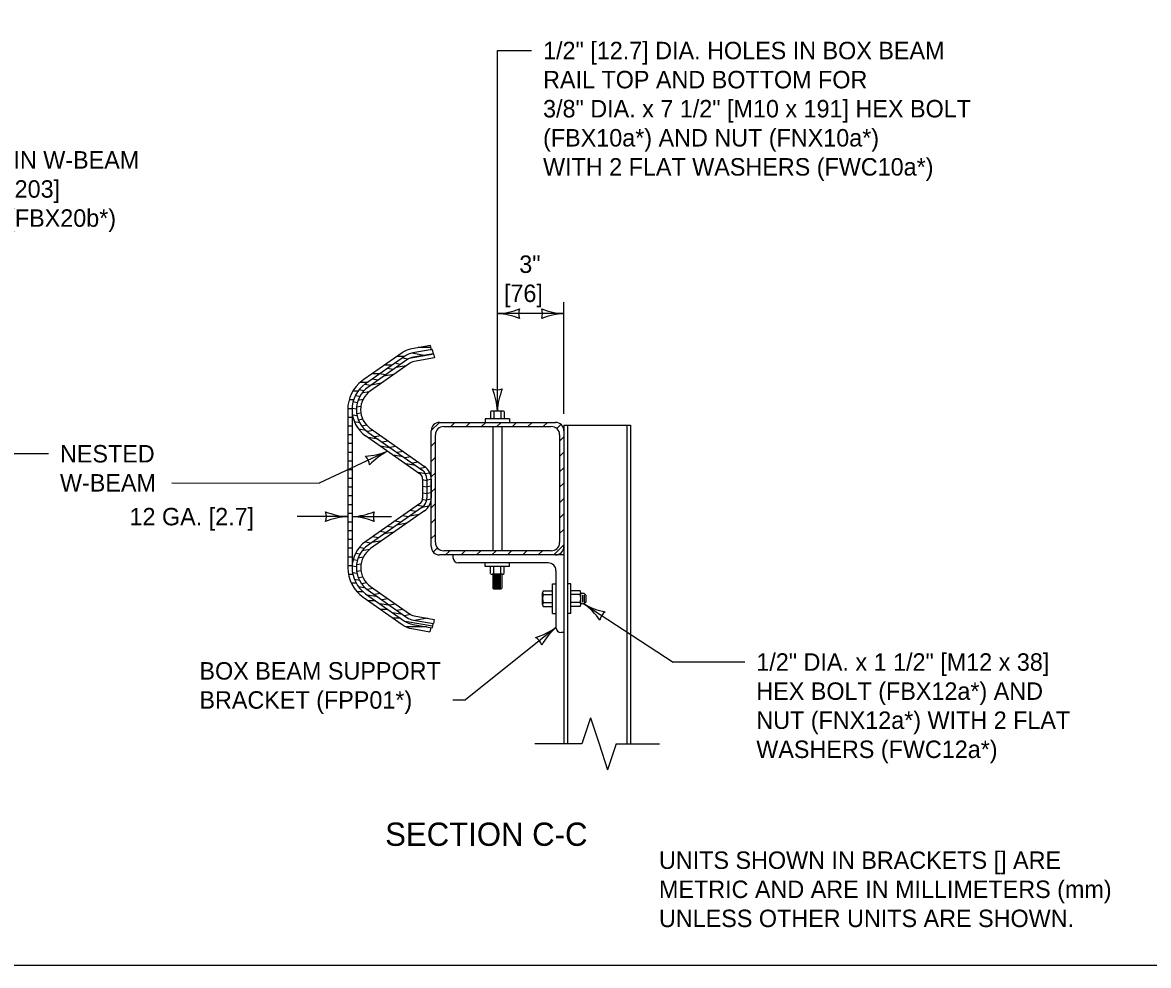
# Model space of a CAD drawing. Extents: x 49991.4 to 50021, y 49987.6 to 50011.4.
# Drawn here: x 50009.364 to 50013.234, y 49987.799 to 49991.041 of the extents above; entities that cross this region are included whole.
import ezdxf

# ---------------------------------------------------------------- set-up
doc = ezdxf.new("R2010")
doc.units = 0
for name, color, linetype in [('Level 1', 7, 'Continuous'), ('Level 2', 7, 'Continuous'), ('Level 3', 7, 'Continuous'), ('Level 6', 7, 'Continuous')]:
    doc.layers.add(name, color=color, linetype=linetype)

msp = doc.modelspace()

# ---------------------------------------------------------------- linework, layer by layer
at = {"layer": 'Level 1'}
for p, q in [((50010.6684, 49989.9052), (50010.5369, 49989.8129)), ((50010.7771, 49989.9002), (50010.6931, 49989.8853)), ((50010.7439, 49989.8964), (50010.7016, 49989.9038)), ((50010.7667, 49989.9304), (50010.7024, 49989.9192)), ((50010.7723, 49989.9164), (50010.7049, 49989.9046)), ((50010.7768, 49989.9021), (50010.7075, 49989.89)), ((50010.7682, 49989.923), (50010.7239, 49989.923)), ((50010.7728, 49989.9139), (50010.7654, 49989.9152)), ((50010.7698, 49989.9159), (50010.7667, 49989.9304)), ((50010.7723, 49989.9164), (50010.7748, 49989.9018)), ((50010.7768, 49989.9021), (50010.7794, 49989.8875)), ((50010.6769, 49989.893), (50010.5424, 49989.7987)), ((50010.6854, 49989.8809), (50010.5509, 49989.7865)), ((50010.6939, 49989.8688), (50010.5594, 49989.7744)), ((50010.634, 49989.863), (50010.6082, 49989.863)), ((50010.6633, 49989.8654), (50010.6427, 49989.8691)), ((50010.6827, 49989.8609), (50010.6482, 49989.8548)), ((50010.6768, 49989.893), (50010.651, 49989.893)), ((50010.6894, 49989.8834), (50010.6684, 49989.8871)), ((50010.7794, 49989.8875), (50010.71, 49989.8754)), ((50010.5912, 49989.833), (50010.5655, 49989.833)), ((50010.6118, 49989.8293), (50010.5912, 49989.833)), ((50010.6396, 49989.8307), (50010.6051, 49989.8246)), ((50010.6376, 49989.8474), (50010.6169, 49989.851)), ((50010.5375, 49989.7747), (50010.5204, 49989.7777)), ((50010.5484, 49989.803), (50010.524, 49989.803)), ((50010.5369, 49989.8129), (50010.5313, 49989.809)), ((50010.5603, 49989.7932), (50010.54, 49989.7968)), ((50010.5424, 49989.7987), (50010.543, 49989.7992)), ((50010.5966, 49989.8006), (50010.5621, 49989.7945)), ((50010.5861, 49989.8113), (50010.5654, 49989.8149)), ((50010.5019, 49989.743), (50010.4863, 49989.743)), ((50010.5169, 49989.773), (50010.4992, 49989.773)), ((50010.5229, 49989.7546), (50010.5075, 49989.7574)), ((50010.5343, 49989.7444), (50010.517, 49989.7413)), ((50010.5547, 49989.7706), (50010.5303, 49989.7663)), ((50010.4816, 49989.7096), (50010.4819, 49989.1665)), ((50010.4966, 49989.713), (50010.4819, 49989.713)), ((50010.4964, 49989.7096), (50010.4967, 49989.1665)), ((50010.5114, 49989.7115), (50010.4967, 49989.7141)), ((50010.5145, 49989.7335), (50010.4999, 49989.7361)), ((50010.5271, 49989.7205), (50010.5118, 49989.7178)), ((50010.9719, 49989.7033), (50010.9719, 49989.6781)), ((50011.0139, 49989.7048), (50010.978, 49989.7048)), ((50010.9838, 49989.7034), (50010.9838, 49989.6781)), ((50011.008, 49989.7034), (50011.008, 49989.6781)), ((50011.0199, 49989.7033), (50011.0199, 49989.6781)), ((50010.4965, 49989.683), (50010.4817, 49989.683)), ((50010.5139, 49989.6885), (50010.4981, 49989.6912)), ((50010.5231, 49989.6643), (50010.5052, 49989.6674)), ((50010.5272, 49989.698), (50010.5124, 49989.6954)), ((50010.5335, 49989.6765), (50010.5184, 49989.6738)), ((50010.7685, 49989.6377), (50010.797, 49989.6661)), ((50010.7973, 49989.6661), (50011.1957, 49989.6661)), ((50010.8356, 49989.6517), (50010.85, 49989.6661)), ((50010.8886, 49989.6517), (50010.903, 49989.6661)), ((50010.9417, 49989.6517), (50010.9561, 49989.6661)), ((50010.9539, 49989.6781), (50010.9539, 49989.6661)), ((50011.0379, 49989.6781), (50010.9539, 49989.6781)), ((50010.9947, 49989.6517), (50011.0091, 49989.6661)), ((50011.0379, 49989.6781), (50011.0379, 49989.6661)), ((50011.0477, 49989.6517), (50011.0621, 49989.6661)), ((50011.1008, 49989.6517), (50011.1152, 49989.6661)), ((50011.1538, 49989.6517), (50011.1682, 49989.6661)), ((50010.4965, 49989.653), (50010.4817, 49989.653)), ((50010.4965, 49989.623), (50010.4817, 49989.623)), ((50010.5445, 49989.6379), (50010.5199, 49989.6422)), ((50010.5469, 49989.6563), (50010.5301, 49989.6533)), ((50010.5696, 49989.6377), (50010.5492, 49989.6341)), ((50010.5509, 49989.6328), (50010.7369, 49989.5026)), ((50010.5594, 49989.6449), (50010.7454, 49989.5148)), ((50010.7685, 49989.2389), (50010.7685, 49989.6373)), ((50010.7829, 49989.2533), (50010.7829, 49989.6229)), ((50010.8117, 49989.6517), (50011.1813, 49989.6517)), ((50010.9809, 49989.6517), (50010.9809, 49989.2245)), ((50011.0109, 49989.6517), (50011.0109, 49989.2245)), ((50011.2, 49989.6449), (50011.2144, 49989.6593)), ((50011.2101, 49989.6229), (50011.2101, 49989.2533)), ((50011.2245, 49989.6559), (50011.4531, 49989.6559)), ((50011.2245, 49989.6559), (50011.2245, 49988.5606)), ((50011.2245, 49989.6373), (50011.2245, 49989.2389)), ((50011.2365, 49989.6559), (50011.2365, 49988.5606)), ((50011.4411, 49989.6559), (50011.4411, 49988.5606)), ((50011.4531, 49989.6559), (50011.4531, 49988.5606)), ((50010.4965, 49989.593), (50010.4817, 49989.593)), ((50010.5431, 49989.62), (50010.5424, 49989.6206)), ((50010.5424, 49989.6206), (50010.7284, 49989.4905)), ((50010.5862, 49989.6079), (50010.5516, 49989.614)), ((50010.5954, 49989.6196), (50010.5747, 49989.616)), ((50010.6212, 49989.6016), (50010.6005, 49989.5979)), ((50010.7685, 49989.5846), (50010.7829, 49989.599)), ((50011.2101, 49989.602), (50011.2245, 49989.6164)), ((50010.4965, 49989.563), (50010.4817, 49989.563)), ((50010.6294, 49989.5777), (50010.5948, 49989.5838)), ((50010.647, 49989.5835), (50010.6263, 49989.5799)), ((50010.6726, 49989.5475), (50010.638, 49989.5536)), ((50010.6728, 49989.5655), (50010.6521, 49989.5619)), ((50010.6986, 49989.5475), (50010.6779, 49989.5438)), ((50010.7685, 49989.5316), (50010.7829, 49989.546)), ((50011.2101, 49989.5489), (50011.2245, 49989.5633)), ((50010.4965, 49989.533), (50010.4817, 49989.533)), ((50010.7159, 49989.5173), (50010.6812, 49989.5234)), ((50010.7244, 49989.5294), (50010.7037, 49989.5258)), ((50010.7495, 49989.5113), (50010.7295, 49989.5077)), ((50011.2101, 49989.4959), (50011.2245, 49989.5103)), ((50010.4965, 49989.503), (50010.4817, 49989.503)), ((50010.4966, 49989.473), (50010.4818, 49989.473)), ((50010.7489, 49989.4889), (50010.7245, 49989.4932)), ((50010.7389, 49989.4703), (50010.7389, 49989.4381)), ((50010.7537, 49989.4655), (50010.7389, 49989.4681)), ((50010.7642, 49989.4913), (50010.749, 49989.4886)), ((50010.7537, 49989.4703), (50010.7537, 49989.4381)), ((50010.7685, 49989.4694), (50010.7537, 49989.4668)), ((50010.7685, 49989.4786), (50010.7829, 49989.493)), ((50010.7685, 49989.4703), (50010.7685, 49989.4381)), ((50010.4966, 49989.443), (50010.4818, 49989.443)), ((50010.7537, 49989.4429), (50010.7389, 49989.4455)), ((50010.7389, 49989.4381), (50010.7389, 49989.4059)), ((50010.7685, 49989.4468), (50010.7537, 49989.4442)), ((50010.7537, 49989.4381), (50010.7537, 49989.4059)), ((50010.7685, 49989.4381), (50010.7685, 49989.4059)), ((50010.7686, 49989.4256), (50010.7829, 49989.4399)), ((50011.2101, 49989.4429), (50011.2245, 49989.4573)), ((50010.4966, 49989.413), (50010.4818, 49989.413)), ((50010.7528, 49989.3978), (50010.7381, 49989.4004)), ((50010.7537, 49989.4203), (50010.7389, 49989.4229)), ((50010.7681, 49989.4016), (50010.7529, 49989.3989)), ((50010.7685, 49989.4243), (50010.7537, 49989.4216)), ((50011.2101, 49989.3898), (50011.2245, 49989.4042)), ((50010.4966, 49989.383), (50010.4818, 49989.383)), ((50010.4966, 49989.353), (50010.4818, 49989.353)), ((50010.7284, 49989.3857), (50010.5434, 49989.2562)), ((50010.7369, 49989.3736), (50010.5519, 49989.2441)), ((50010.7454, 49989.3614), (50010.5604, 49989.2319)), ((50010.7162, 49989.3591), (50010.6956, 49989.3628)), ((50010.7412, 49989.3773), (50010.7213, 49989.3808)), ((50010.7606, 49989.3777), (50010.7367, 49989.3735)), ((50010.7685, 49989.3725), (50010.7829, 49989.3869)), ((50010.4966, 49989.323), (50010.4818, 49989.323)), ((50010.6647, 49989.323), (50010.644, 49989.3267)), ((50010.685, 49989.3192), (50010.6505, 49989.3131)), ((50010.6905, 49989.3411), (50010.6698, 49989.3447)), ((50010.7282, 49989.3494), (50010.6936, 49989.3433)), ((50010.7685, 49989.3195), (50010.7829, 49989.3339)), ((50011.2101, 49989.3368), (50011.2245, 49989.3512)), ((50010.4966, 49989.293), (50010.4818, 49989.293)), ((50010.6131, 49989.2869), (50010.5925, 49989.2906)), ((50010.6419, 49989.289), (50010.6073, 49989.2829)), ((50010.6389, 49989.305), (50010.6182, 49989.3086)), ((50010.7685, 49989.2664), (50010.7829, 49989.2808)), ((50011.2101, 49989.2838), (50011.2245, 49989.2982)), ((50010.4967, 49989.263), (50010.4819, 49989.263)), ((50010.5616, 49989.2509), (50010.5411, 49989.2545)), ((50010.5988, 49989.2588), (50010.5642, 49989.2527)), ((50010.5874, 49989.2689), (50010.5667, 49989.2725)), ((50011.1895, 49989.2101), (50011.2245, 49989.2451)), ((50010.4967, 49989.233), (50010.4819, 49989.233)), ((50010.4967, 49989.203), (50010.4819, 49989.203)), ((50010.5236, 49989.2124), (50010.5082, 49989.2151)), ((50010.5351, 49989.2024), (50010.5176, 49989.1993)), ((50010.5384, 49989.2323), (50010.5212, 49989.2354)), ((50010.5565, 49989.2287), (50010.5314, 49989.2243)), ((50010.7754, 49989.2203), (50010.7898, 49989.2347)), ((50011.1957, 49989.2101), (50010.7973, 49989.2101)), ((50011.1813, 49989.2245), (50010.8117, 49989.2245)), ((50010.8183, 49989.2101), (50010.8327, 49989.2245)), ((50011.2245, 49989.2101), (50010.8435, 49989.2101)), ((50010.8435, 49989.2101), (50010.8435, 49989.2011)), ((50010.8713, 49989.2101), (50010.8857, 49989.2245)), ((50010.9243, 49989.2101), (50010.9387, 49989.2245)), ((50010.9774, 49989.2101), (50010.9918, 49989.2245)), ((50011.0304, 49989.2101), (50011.0448, 49989.2245)), ((50011.0834, 49989.2101), (50011.0978, 49989.2245)), ((50011.1365, 49989.2101), (50011.1509, 49989.2245)), ((50010.4967, 49989.173), (50010.4819, 49989.173)), ((50010.5117, 49989.1693), (50010.4969, 49989.1719)), ((50010.5149, 49989.1913), (50010.5004, 49989.1939)), ((50010.5275, 49989.1784), (50010.5122, 49989.1757)), ((50011.1705, 49989.1831), (50010.8615, 49989.1831)), ((50010.9539, 49989.1711), (50010.9539, 49989.1831)), ((50011.0379, 49989.1711), (50010.9539, 49989.1711)), ((50010.9719, 49989.1459), (50010.9719, 49989.1711)), ((50010.9838, 49989.1458), (50010.9838, 49989.1711)), ((50011.008, 49989.1458), (50011.008, 49989.1711)), ((50011.0199, 49989.1459), (50011.0199, 49989.1711)), ((50011.0379, 49989.1711), (50011.0379, 49989.1831)), ((50010.4996, 49989.143), (50010.4845, 49989.143)), ((50010.5139, 49989.1463), (50010.4983, 49989.1491)), ((50010.5228, 49989.1221), (50010.505, 49989.1253)), ((50010.5273, 49989.1558), (50010.5125, 49989.1532)), ((50010.5333, 49989.1343), (50010.5184, 49989.1317)), ((50011.0139, 49989.1444), (50010.978, 49989.1444)), ((50010.9809, 49989.1444), (50010.9809, 49989.0961)), ((50011.0079, 49989.1411), (50010.9839, 49989.1411)), ((50011.0079, 49989.1366), (50010.9839, 49989.1366)), ((50011.0079, 49989.1321), (50010.9839, 49989.1321)), ((50011.0079, 49989.1276), (50010.9839, 49989.1276)), ((50011.0079, 49989.1231), (50010.9839, 49989.1231)), ((50011.0109, 49989.1444), (50011.0109, 49989.0961)), ((50011.1975, 49989.1561), (50011.1975, 49988.9611)), ((50010.5111, 49989.113), (50010.4943, 49989.113)), ((50010.5357, 49989.083), (50010.5146, 49989.083)), ((50010.5433, 49989.0959), (50010.5194, 49989.1002)), ((50010.5463, 49989.114), (50010.5298, 49989.1111)), ((50010.5687, 49989.0954), (50010.5485, 49989.0918)), ((50010.5518, 49989.0891), (50010.6854, 49988.9952)), ((50010.5603, 49989.1012), (50010.6939, 49989.0074)), ((50010.9839, 49989.0931), (50010.9809, 49989.0961)), ((50011.0079, 49989.1186), (50010.9839, 49989.1186)), ((50011.0079, 49989.1141), (50010.9839, 49989.1141)), ((50011.0079, 49989.1096), (50010.9839, 49989.1096)), ((50011.0079, 49989.1051), (50010.9839, 49989.1051)), ((50011.0079, 49989.1006), (50010.9839, 49989.1006)), ((50011.0079, 49989.0961), (50010.9839, 49989.0961)), ((50011.0079, 49989.0931), (50010.9839, 49989.0931)), ((50011.0109, 49989.0961), (50011.0079, 49989.0931)), ((50011.1531, 49989.0871), (50011.1855, 49989.0871)), ((50011.1855, 49989.1111), (50011.1975, 49989.1111)), ((50011.1855, 49989.0091), (50011.1855, 49989.1111)), ((50011.2485, 49989.1111), (50011.2365, 49989.1111)), ((50011.2485, 49989.0091), (50011.2485, 49989.1111)), ((50011.2809, 49989.0871), (50011.2485, 49989.0871)), ((50010.5347, 49989.0649), (50010.6683, 49988.971)), ((50010.5433, 49989.077), (50010.6769, 49988.9831)), ((50010.5846, 49989.0661), (50010.5501, 49989.0722)), ((50010.5774, 49989.053), (50010.5517, 49989.053)), ((50010.5944, 49989.0773), (50010.5738, 49989.0737)), ((50010.6201, 49989.0592), (50010.5995, 49989.0556)), ((50011.1514, 49989.0399), (50011.1514, 49989.0803)), ((50011.1531, 49989.0737), (50011.1855, 49989.0737)), ((50011.1531, 49989.0465), (50011.1855, 49989.0465)), ((50011.281, 49989.0737), (50011.2485, 49989.0737)), ((50011.281, 49989.0465), (50011.2485, 49989.0465)), ((50011.2826, 49989.0399), (50011.2826, 49989.0803)), ((50011.2935, 49989.0781), (50011.2826, 49989.0781)), ((50011.289, 49989.0721), (50011.289, 49989.0481)), ((50011.2995, 49989.0721), (50011.2935, 49989.0781)), ((50011.2995, 49989.0481), (50011.2935, 49989.0421)), ((50011.2943, 49989.0721), (50011.2943, 49989.0481)), ((50011.2995, 49989.0721), (50011.2995, 49989.0481)), ((50010.6275, 49989.0359), (50010.593, 49989.042)), ((50010.6201, 49989.023), (50010.5944, 49989.023)), ((50010.6458, 49989.0412), (50010.6252, 49989.0375)), ((50010.6704, 49989.0058), (50010.636, 49989.0118)), ((50010.6715, 49989.0231), (50010.6509, 49989.0195)), ((50010.6979, 49989.0052), (50010.6766, 49989.0014)), ((50011.1531, 49989.0331), (50011.1855, 49989.0331)), ((50011.1855, 49989.0091), (50011.1975, 49989.0091)), ((50011.2485, 49989.0091), (50011.2365, 49989.0091)), ((50011.2809, 49989.0331), (50011.2485, 49989.0331)), ((50011.2935, 49989.0421), (50011.2826, 49989.0421)), ((50010.6628, 49988.993), (50010.6371, 49988.993)), ((50010.7729, 49988.9651), (50010.6793, 49988.9816)), ((50010.7049, 49988.9715), (50010.772, 49988.9598)), ((50010.7075, 49988.9861), (50010.7768, 49988.974)), ((50010.71, 49989.0008), (50010.7793, 49988.9886)), ((50010.7556, 49988.9928), (50010.7127, 49988.9852)), ((50010.7746, 49988.9744), (50010.772, 49988.9598)), ((50010.7793, 49988.9886), (50010.7768, 49988.974)), ((50010.7537, 49988.963), (50010.6833, 49988.963)), ((50010.7025, 49988.9569), (50010.7023, 49988.957)), ((50010.7023, 49988.957), (50010.7644, 49988.9461)), ((50010.7668, 49988.9607), (50010.7644, 49988.9461)), ((50011.2245, 49988.9431), (50011.2155, 49988.9431))]:
    msp.add_line(p, q, dxfattribs=at)
msp.add_lwpolyline([(49999.3835, 49998.9992), (50016.7501, 49998.9992), (50016.7501, 49987.7988), (49999.3835, 49987.7988)], close=True, dxfattribs=at)
for centre, radius, start, end in [((50010.7166, 49989.8364), 0.084, 99.7276, 125.0905), ((50010.7166, 49989.8364), 0.0692, 99.7276, 125.0905), ((50010.7166, 49989.8364), 0.0544, 99.7276, 125.0905), ((50010.7166, 49989.8364), 0.0396, 99.7276, 125.0905), ((50010.6059, 49989.7096), 0.1242, 126.8825, 180.0271), ((50010.6059, 49989.7096), 0.1094, 125.0494, 235.0019), ((50010.6059, 49989.7096), 0.0946, 125.0494, 235.0019), ((50010.6059, 49989.7096), 0.0798, 125.0494, 235.0019), ((50010.7973, 49989.6373), 0.0288, 90, 180), ((50011.1957, 49989.6373), 0.0288, 0, 90), ((50010.8117, 49989.6229), 0.0288, 90, 180), ((50011.1813, 49989.6229), 0.0288, 0, 90), ((50010.7142, 49989.4703), 0.0543, 0, 54.9777), ((50010.7142, 49989.4703), 0.0247, 0, 54.9777), ((50010.7142, 49989.4703), 0.0395, 0, 54.9777), ((50010.7142, 49989.4059), 0.0247, 305.0223, 0), ((50010.7142, 49989.4059), 0.0395, 305.0223, 0), ((50010.7142, 49989.4059), 0.0543, 305.0223, 0), ((50010.6062, 49989.1666), 0.1095, 124.9844, 234.9352), ((50010.6062, 49989.1666), 0.0946, 124.9844, 234.9352), ((50010.7973, 49989.2389), 0.0288, 180, 270), ((50010.8117, 49989.2533), 0.0288, 180, 270), ((50011.1813, 49989.2533), 0.0288, 270, 0), ((50011.1957, 49989.2389), 0.0288, 270, 0), ((50010.6062, 49989.1666), 0.0798, 124.9844, 234.9352), ((50010.8615, 49989.2011), 0.018, 180, 270), ((50010.6062, 49989.1666), 0.1243, 180.027, 234.9352), ((50011.1705, 49989.1561), 0.027, 0, 90), ((50010.7166, 49989.0397), 0.0396, 234.9095, 260.2724), ((50010.7166, 49989.0397), 0.084, 234.9095, 260.2724), ((50010.7166, 49989.0397), 0.0692, 234.9095, 260.2724), ((50010.7166, 49989.0397), 0.0544, 234.9095, 260.2724), ((50011.2155, 49988.9611), 0.018, 180, 270)]:
    msp.add_arc(centre, radius, start, end, dxfattribs=at)
for centre, major_axis, start_param, end_param in [((50010.9779, 49989.6936), (-0.012, 0), 4.198439, 5.235988), ((50010.9959, 49989.6598), (-0.048, 0), 4.457545, 4.967234), ((50011.0139, 49989.6936), (-0.012, 0), 4.188789, 5.226338), ((50010.9779, 49989.1556), (-0.012, 0), 1.047198, 2.084746), ((50010.9959, 49989.1894), (-0.048, 0), 1.315951, 1.825641), ((50011.0139, 49989.1556), (-0.012, 0), 1.056847, 2.094396), ((50011.1641, 49989.0803), (0, 0.0135), 1.047198, 2.084746), ((50011.27, 49989.0803), (0, 0.0135), 4.198439, 5.235988), ((50011.202, 49989.0601), (0, 0.054), 1.315951, 1.825641), ((50011.1641, 49989.0398), (0, 0.0135), 1.056847, 2.094396), ((50011.27, 49989.0398), (0, 0.0135), 4.188789, 5.226338), ((50011.232, 49989.0601), (0, 0.054), 4.457545, 4.967234)]:
    msp.add_ellipse(centre, major_axis=major_axis, ratio=0.93686, start_param=start_param, end_param=end_param, dxfattribs=at)
at = {"layer": 'Level 3'}
for p, q in [((50010.996, 49989.7048), (50010.996, 49990.9445)), ((50010.996, 49990.9445), (50011.1131, 49990.9445)), ((50011.2245, 49989.6959), (50011.2245, 49990.0798)), ((50011.2245, 49990.0398), (50010.996, 49990.0398)), ((50009.4528, 49989.5582), (50009.2298, 49989.5582)), ((50010.6189, 49989.5671), (50010.3839, 49989.4575)), ((50009.8772, 49989.4582), (50010.3839, 49989.4575)), ((50010.4818, 49989.342), (50010.3074, 49989.342)), ((50010.4966, 49989.3421), (50010.6327, 49989.3421)), ((50011.2935, 49989.0421), (50011.6001, 49988.8421)), ((50011.1975, 49988.9611), (50010.8862, 49988.7117)), ((50011.846, 49988.8421), (50011.6001, 49988.8421)), ((50010.8424, 49988.7117), (50010.8862, 49988.7117))]:
    msp.add_line(p, q, dxfattribs=at)
for centre, radius, start, end in [((50010.9868, 49990.2619), 0.2223, 272.3605, 292.544), ((50011.1242, 49990.0398), 0.0548, 162.1388, 197.8612), ((50011.0963, 49990.0398), 0.0548, 342.1388, 17.8612), ((50011.236, 49990.2725), 0.233, 247.9228, 267.1727), ((50010.9845, 49989.807), 0.233, 67.9228, 87.1727), ((50011.2337, 49989.8176), 0.2223, 92.3605, 112.544), ((50010.7738, 49989.6956), 0.2223, 2.3605, 22.544), ((50010.996, 49989.833), 0.0548, 252.1388, 287.8612), ((50011.2287, 49989.6933), 0.233, 157.9228, 177.1727), ((50010.5333, 49989.7723), 0.2223, 272.4592, 292.6427), ((50010.5027, 49989.5129), 0.0548, 7.142, 42.8644), ((50010.7277, 49989.3611), 0.233, 117.8305, 137.0804), ((50010.491, 49989.5642), 0.2223, 247.456, 267.6395), ((50010.3536, 49989.342), 0.0548, 342.1388, 17.8612), ((50010.4851, 49989.5748), 0.233, 272.8273, 292.0772), ((50010.6248, 49989.3421), 0.0548, 162.1388, 197.8612), ((50010.4933, 49989.1093), 0.233, 92.8273, 112.0772), ((50010.4875, 49989.1199), 0.2223, 67.456, 87.6395), ((50011.4072, 49989.2332), 0.2223, 239.2466, 259.4301), ((50011.1568, 49988.8535), 0.233, 34.8089, 54.0588), ((50011.4009, 49988.9721), 0.0548, 129.0249, 164.7473), ((50011.061, 49989.1499), 0.233, 286.6136, 305.8634), ((50011.0975, 49988.881), 0.0548, 20.8296, 56.5519), ((50011.3435, 49988.7934), 0.2223, 131.0512, 151.2347)]:
    msp.add_arc(centre, radius, start, end, dxfattribs=at)
at = {"layer": 'Level 6'}
for p, q in [((50011.316, 49988.6502), (50011.2865, 49988.5606)), ((50011.316, 49988.6502), (50011.3455, 49988.5606)), ((50011.2865, 49988.5606), (50011.1245, 49988.5606)), ((50011.3455, 49988.5606), (50011.375, 49988.471)), ((50011.4045, 49988.5606), (50011.375, 49988.471)), ((50011.4045, 49988.5606), (50011.5531, 49988.5606))]:
    msp.add_line(p, q, dxfattribs=at)

# ---------------------------------------------------------------- texts
at = {"layer": 'Level 2'}
for s, height, p in [('1/2" [12.7] DIA. HOLES IN BOX BEAM', 0.06, (50011.1531, 49990.9145)), ('RAIL TOP AND BOTTOM FOR', 0.06, (50011.1531, 49990.8145)), ('3/8" DIA. x 7 1/2" [M10 x 191] HEX BOLT ', 0.06, (50011.1531, 49990.7145)), ('(FBX10a*) AND NUT (FNX10a*) ', 0.06, (50011.1531, 49990.6145)), ('7/8" x 2 1/2" [22.2 x 63.5] SLOT IN W-BEAM', 0.06, (50008.1831, 49990.5385)), ('WITH 2 FLAT WASHERS (FWC10a*)', 0.06, (50011.1531, 49990.5145)), ('RAIL FOR 3/4" DIA. x 8" [M20 x 203] ', 0.06, (50008.1831, 49990.4385)), ('HIGH STRENGTH HEX BOLT  (FBX20b*)', 0.06, (50008.1831, 49990.3385)), ('3"', 0.06, (50011.0713, 49990.1798)), ('[76]', 0.06, (50011.0184, 49990.0798)), ('NESTED ', 0.06, (50009.4928, 49989.5282)), ('W-BEAM', 0.06, (50009.4928, 49989.4282)), ('12 GA. [2.7]', 0.06, (50009.7318, 49989.312)), ('1/2" DIA. x 1 1/2" [M12 x 38]', 0.06, (50011.886, 49988.8121)), ('HEX BOLT (FBX12a*) AND', 0.06, (50011.886, 49988.7121)), ('NUT (FNX12a*) WITH 2 FLAT ', 0.06, (50011.886, 49988.6121)), ('WASHERS (FWC12a*)', 0.06, (50011.886, 49988.5121)), ('SECTION C-C', 0.08, (50010.6104, 49988.2101)), ('UNITS SHOWN IN BRACKETS [] ARE ', 0.06, (50011.5514, 49988.1308)), ('METRIC AND ARE IN MILLIMETERS (mm) ', 0.06, (50011.5514, 49988.0308)), ('UNLESS OTHER UNITS ARE SHOWN.', 0.06, (50011.5514, 49987.9308))]:
    msp.add_text(s, height=height, dxfattribs=at).set_placement(p)
for s, p in [('BOX BEAM SUPPORT', (50009.9721, 49988.7817)), ('BRACKET (FPP01*)', (50009.9721, 49988.6817))]:
    msp.add_text(s, height=0.06, rotation=360, dxfattribs=at).set_placement(p)

doc.saveas('drawing.dxf')
